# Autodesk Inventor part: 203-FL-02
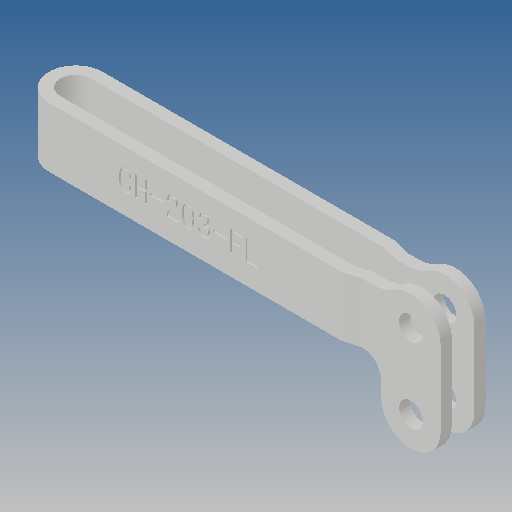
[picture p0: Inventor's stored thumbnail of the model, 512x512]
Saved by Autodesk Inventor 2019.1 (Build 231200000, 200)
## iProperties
Created: 2012-09
Part Number: 203-FL-02
Material: Ogólny
Document SubType Name: Modeling
Designer: CADENGINEERING4
Density: 1 g/cm^3
Appearance: Domyślna
Author: CADENGINEERING4
Revision Number: ÈÎºÎ
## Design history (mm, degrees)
feature "ÇÐ³ý-À­Éì5"
node "Bryła1"
